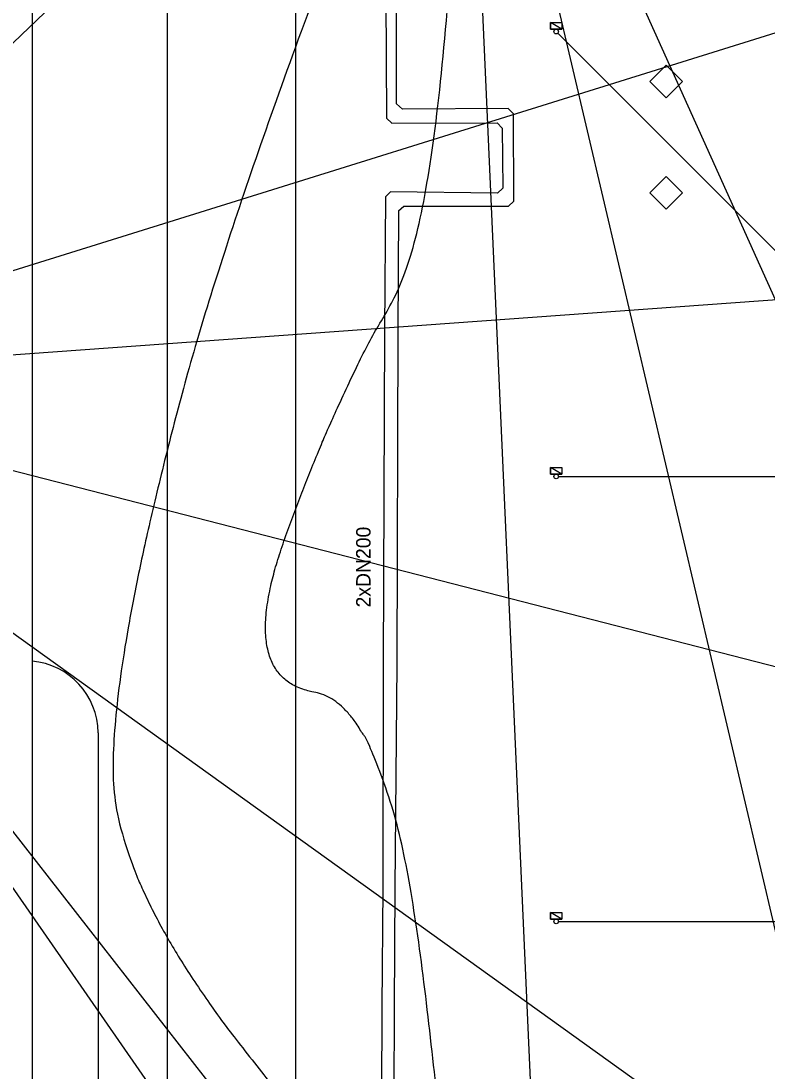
# Model space of a CAD drawing. Extents: x -264090 to -263500, y -1242327 to -1242030.
# Drawn here: x -263959.94 to -263927.74, y -1242142.01 to -1242096.69 of the extents above; entities that cross this region are included whole.
import ezdxf

# ---------------------------------------------------------------- set-up
doc = ezdxf.new("R2010")
doc.units = 0
for name, color, linetype in [('KFA_KOORD_SIT_a_IS_SEDA', 7, 'Continuous'), ('KFA_ZVS_NIVELACIA', 7, 'Continuous'), ('KFA_ZVS_SMERY_A_DLZKY', 7, 'Continuous')]:
    doc.layers.add(name, color=color, linetype=linetype)

msp = doc.modelspace()

# ---------------------------------------------------------------- linework, layer by layer
at = {"layer": 'KFA_KOORD_SIT_a_IS_SEDA'}
for p, q in [((-263959.468, -1242059.534), (-263959.468, -1242179.482)), ((-263944.262, -1242086.274), (-263944.165, -1242100.884)), ((-263943.732, -1242100.264), (-263943.748, -1242086.382)), ((-263948.093, -1242087.901), (-263948.093, -1242241.458)), ((-263953.617, -1242244.458), (-263953.617, -1242093.307)), ((-263937.093, -1242097.052), (-263937.093, -1242096.762)), ((-263937.093, -1242096.762), (-263936.593, -1242096.762)), ((-263936.593, -1242097.052), (-263937.093, -1242096.762)), ((-263936.593, -1242097.052), (-263937.093, -1242096.762)), ((-263937.093, -1242096.762), (-263937.093, -1242097.052)), ((-263936.593, -1242096.762), (-263936.593, -1242097.052)), ((-263936.593, -1242097.052), (-263937.093, -1242097.052)), ((-263937.093, -1242097.052), (-263936.593, -1242097.052)), ((-263936.772, -1242097.223), (-263926.946, -1242107.049)), ((-263932.8, -1242099.307), (-263932.093, -1242098.6)), ((-263932.093, -1242098.6), (-263931.386, -1242099.307)), ((-263932.093, -1242098.6), (-263932.093, -1242098.6)), ((-263932.093, -1242100.014), (-263932.8, -1242099.307)), ((-263931.386, -1242099.307), (-263932.093, -1242100.014)), ((-263943.479, -1242100.5), (-263943.732, -1242100.264)), ((-263938.913, -1242100.478), (-263943.479, -1242100.5)), ((-263938.679, -1242100.702), (-263938.913, -1242100.478)), ((-263938.67, -1242104.473), (-263938.679, -1242100.702)), ((-263944.165, -1242100.884), (-263943.933, -1242101.097)), ((-263943.933, -1242101.097), (-263939.391, -1242101.095)), ((-263939.391, -1242101.095), (-263939.173, -1242101.317)), ((-263939.173, -1242101.317), (-263939.148, -1242103.915)), ((-263932.8, -1242104.107), (-263932.093, -1242103.4)), ((-263932.093, -1242103.4), (-263931.386, -1242104.107)), ((-263932.093, -1242103.4), (-263932.093, -1242103.4)), ((-263939.148, -1242103.915), (-263939.372, -1242104.13)), ((-263944.203, -1242104.281), (-263944.247, -1242110.034)), ((-263943.995, -1242104.067), (-263944.203, -1242104.281)), ((-263939.372, -1242104.13), (-263943.995, -1242104.067)), ((-263938.898, -1242104.687), (-263938.67, -1242104.473)), ((-263932.093, -1242104.814), (-263932.8, -1242104.107)), ((-263931.386, -1242104.107), (-263932.093, -1242104.814)), ((-263943.643, -1242104.893), (-263943.683, -1242110.091)), ((-263943.643, -1242104.893), (-263943.421, -1242104.68)), ((-263943.421, -1242104.68), (-263938.898, -1242104.687)), ((-263944.247, -1242110.034), (-263944.306, -1242124.434)), ((-263943.683, -1242110.091), (-263943.723, -1242124.445)), ((-263937.093, -1242116.252), (-263937.093, -1242115.962)), ((-263937.093, -1242115.962), (-263936.593, -1242115.962)), ((-263936.593, -1242116.252), (-263937.093, -1242115.962)), ((-263936.593, -1242116.252), (-263937.093, -1242115.962)), ((-263937.093, -1242115.962), (-263937.093, -1242116.252)), ((-263936.593, -1242116.252), (-263937.093, -1242116.252)), ((-263937.093, -1242116.252), (-263936.593, -1242116.252)), ((-263936.593, -1242115.962), (-263936.593, -1242116.252)), ((-263936.743, -1242116.352), (-263926.953, -1242116.352)), ((-263959.468, -1242124.318), (-263959.468, -1242124.318)), ((-263944.306, -1242124.434), (-263944.326, -1242134.105)), ((-263943.723, -1242124.445), (-263943.809, -1242134.109)), ((-263956.618, -1242127.418), (-263956.618, -1242162.449)), ((-263944.326, -1242134.105), (-263944.369, -1242139.25)), ((-263943.809, -1242134.109), (-263943.839, -1242139.271)), ((-263937.092, -1242135.452), (-263937.092, -1242135.162)), ((-263937.092, -1242135.162), (-263936.592, -1242135.162)), ((-263936.592, -1242135.452), (-263937.092, -1242135.162)), ((-263936.592, -1242135.452), (-263937.092, -1242135.162)), ((-263937.092, -1242135.162), (-263937.092, -1242135.452)), ((-263936.592, -1242135.162), (-263936.592, -1242135.452)), ((-263936.592, -1242135.452), (-263937.092, -1242135.452)), ((-263937.092, -1242135.452), (-263936.592, -1242135.452)), ((-263936.743, -1242135.552), (-263926.953, -1242135.552)), ((-263944.369, -1242139.25), (-263944.386, -1242147.884)), ((-263943.839, -1242139.271), (-263943.869, -1242147.889))]:
    msp.add_line(p, q, dxfattribs=at)
for centre in [(-263936.843, -1242097.152), (-263936.843, -1242116.352), (-263936.843, -1242135.552)]:
    msp.add_circle(centre, 0.1, dxfattribs=at)
msp.add_arc((-263959.738, -1242127.427), 3.12, 0.1518, 85.0363, dxfattribs=at)
at = {"layer": 'KFA_ZVS_NIVELACIA'}
for points in [[(-263940.788, -1242078.938), (-263950.124, -1242102.026), (-263955.973, -1242123.929), (-263955.973, -1242134.13), (-263943.376, -1242149.689), (-263946.118, -1242158.004), (-263936.802, -1242167.947)], [(-263936.802, -1242167.947), (-263938.18, -1242161.645), (-263941.069, -1242151.603), (-263943.851, -1242126.263), (-263950.707, -1242125.062), (-263946.422, -1242113.061), (-263941.281, -1242104.232), (-263940.788, -1242078.938)]]:
    msp.add_open_spline(points, degree=2, dxfattribs=at)
at = {"layer": 'KFA_ZVS_SMERY_A_DLZKY'}
for p, q in [((-263854.005, -1242074.334), (-263975.491, -1242112.207)), ((-263940.788, -1242078.938), (-263975.491, -1242112.207)), ((-263936.802, -1242167.947), (-263940.788, -1242078.938)), ((-263858.267, -1242262.294), (-263940.788, -1242078.938)), ((-263940.788, -1242078.938), (-263916.904, -1242180.641)), ((-263779.167, -1242098.021), (-263975.491, -1242112.207)), ((-263936.802, -1242167.947), (-263975.491, -1242112.207)), ((-263786.209, -1242248.09), (-263975.491, -1242112.207)), ((-263858.267, -1242262.294), (-263975.491, -1242112.207)), ((-263768.002, -1242165.53), (-263975.491, -1242112.207))]:
    msp.add_line(p, q, dxfattribs=at)

# ---------------------------------------------------------------- texts
at = {"layer": 'KFA_KOORD_SIT_a_IS_SEDA'}
msp.add_text('2xDN200', height=0.625, rotation=90, dxfattribs=at).set_placement((-263944.853, -1242122.004))

doc.saveas('drawing.dxf')
